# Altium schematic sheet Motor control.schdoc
size 438 x 304 mm
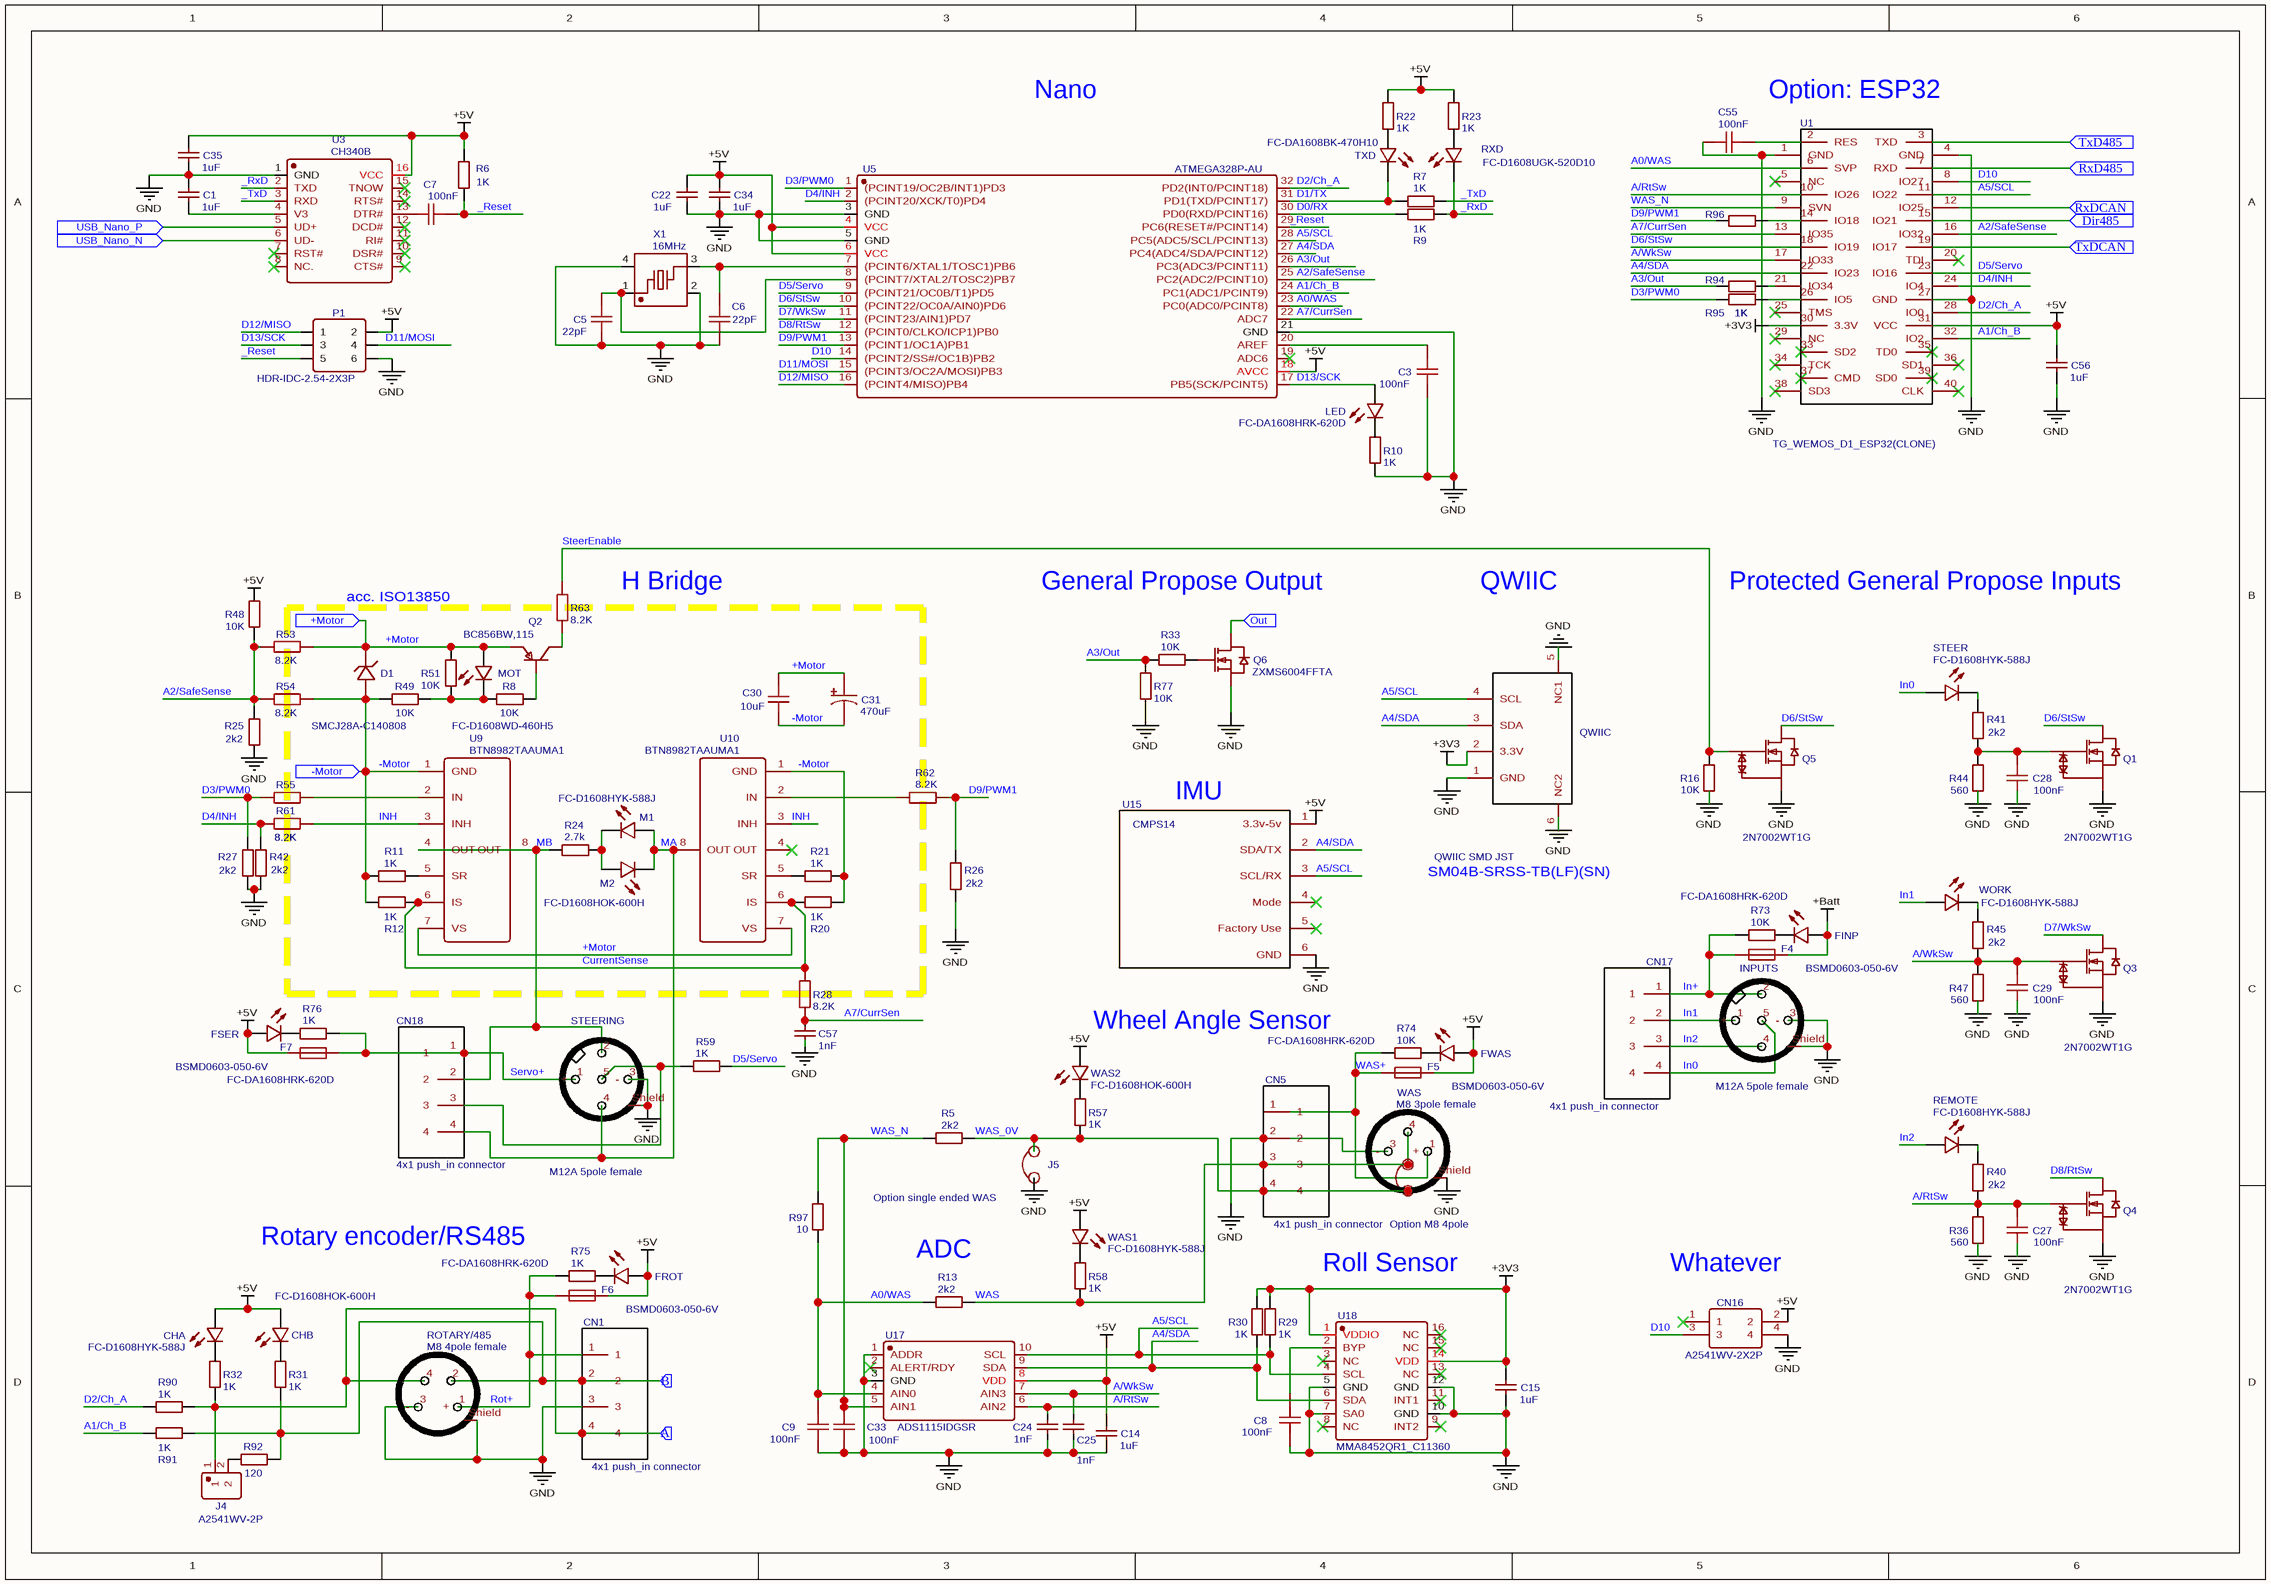
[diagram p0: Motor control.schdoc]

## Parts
C1  1uF  [C0603]
C3  100nF  [C0603]
C5  22pF  [C0603]
C6  22pF  [C0603]
C7  100nF  [C0603]
C8  100nF  [C0603]
C9  100nF  [C0603]
C14  1uF  [C0603]
C15  1uF  [C0603]
C22  1uF  [C0603]
C24  1nF  [C0603]
C25  1nF  [C0603]
C27  100nF  [C0603]
C28  100nF  [C0603]
C29  100nF  [C0603]
C30  10uF  [C1206]
C31  470uF  [CAP-SMD_BD10.0-L10.3-W10.3-FD]
C33  100nF  [C0603]
C34  1uF  [C0603]
C35  1uF  [C0603]
C55  100nF  [C0603]
C56  1uF  [C0603]
C57  1nF  [C0603]
CHA  FC-D1608HYK-588J  [LED0603-RD]
CHB  FC-D1608HOK-600H  [LED0603-RD]
CN1  4x1 push_in connector  [S2C-SMT 3.50/04/180G 3.5SN BK RL]
CN5  4x1 push_in connector  [S2C-SMT 3.50/04/180G 3.5SN BK RL]
CN16  A2541WV-2X2P  [HDR-TH_4P-P2.54-V-R2-C2-S2.54_A2541WV-2X2P]
CN17  4x1 push_in connector  [S2C-SMT 3.50/04/180G 3.5SN BK RL]
CN18  4x1 push_in connector  [S2C-SMT 3.50/04/180G 3.5SN BK RL]
D1  SMCJ28A-C140808  [SMC_L6.9-W5.9-LS7.9-RD]
F4  BSMD0603-050-6V  [F0603]
F5  BSMD0603-050-6V  [F0603]
F6  BSMD0603-050-6V  [F0603]
F7  BSMD0603-050-6V  [F0603]
FINP  FC-DA1608HRK-620D  [LED0603-FD]
FROT  FC-DA1608HRK-620D  [LED0603-FD]
FSER  FC-DA1608HRK-620D  [LED0603-FD]
FWAS  FC-DA1608HRK-620D  [LED0603-FD]
INPUTS  M12A 5pole female  [M12-A FEMALE 4-5POLE 90°]
J4  A2541WV-2P  [HDR-TH_P2.54-H-M_A2541WV-2P]
J5  Option single ended WAS  [1X02]
LED  FC-DA1608HRK-620D  [LED0603-FD]
M1  FC-D1608HYK-588J  [LED0603-RD]
M2  FC-D1608HOK-600H  [LED0603-RD]
MOT  FC-D1608WD-460H5  [LED0603-RD]
OP1  Option M8 4pole  [1X02]
P1  HDR-IDC-2.54-2X3P  [IDC-TH_6P-P2.54_C11214]
Q1  2N7002WT1G  [SOT-323-3_L2.0-W1.3-P1.30-LS2.1-BR]
Q2  BC856BW,115  [SOT-323-3_L2.2-W1.3-P1.30-LS2.2-BR]
Q3  2N7002WT1G  [SOT-323-3_L2.0-W1.3-P1.30-LS2.1-BR]
Q4  2N7002WT1G  [SOT-323-3_L2.0-W1.3-P1.30-LS2.1-BR]
Q5  2N7002WT1G  [SOT-323-3_L2.0-W1.3-P1.30-LS2.1-BR]
Q6  ZXMS6004FFTA  [SOT-23-3_L2.9-W1.6-P1.90-LS2.8-BR]
QWIIC  QWIIC SMD JST  [QWIIC CONNECTOR]
R5  2k2  [R0603]
R6  1K  [R0603]
R7  1K  [R0603]
R8  10K  [R0603]
R9  1K  [R0603]
R10  1K  [R0603]
R11  1K  [R0603]
R12  1K  [R0603]
R13  2k2  [R0603]
R16  10K  [R0603]
R20  1K  [R0603]
R21  1K  [R0603]
R22  1K  [R0603]
R23  1K  [R0603]
R24  2.7k  [R0603]
R25  2k2  [R0603]
R26  2k2  [R0603]
R27  2k2  [R0603]
R28  8.2K  [RES-SMD_L3.5-W1.5]
R29  1K  [R0603]
R30  1K  [R0603]
R31  1K  [R0603]
R32  1K  [R0603]
R33  10K  [R0603]
R36  560  [R0603]
R40  2k2  [R0603]
R41  2k2  [R0603]
R42  2k2  [R0603]
R44  560  [R0603]
R45  2k2  [R0603]
R47  560  [R0603]
R48  10K  [R0603]
R49  10K  [R0603]
R51  10K  [R0603]
R53  8.2K  [RES-SMD_L3.5-W1.5]
R54  8.2K  [RES-SMD_L3.5-W1.5]
R55  8.2K  [RES-SMD_L3.5-W1.5]
R57  1K  [R0603]
R58  1K  [R0603]
R59  1K  [R0603]
R61  8.2K  [RES-SMD_L3.5-W1.5]
R62  8.2K  [RES-SMD_L3.5-W1.5]
R63  8.2K  [RES-SMD_L3.5-W1.5]
R73  10K  [R0603]
R74  10K  [R0603]
R75  1K  [R0603]
R76  1K  [R0603]
R77  10K  [R0603]
R90  1K  [R0603]
R91  1K  [R0603]
R92  120  [R1206]
R94  1K  [R0603]
R95  1K  [R0603]
R96  1K  [R0603]
R97  10  [R0603]
REMOTE  FC-D1608HYK-588J  [LED0603-RD]
ROTARY/485  M8 4pole female  [M8 FEMALE 4POLE 90°]
RXD  FC-D1608UGK-520D10  [LED0603-RD]
STEER  FC-D1608HYK-588J  [LED0603-RD]
STEERING  M12A 5pole female  [M12-A FEMALE 4-5POLE 90°]
TXD  FC-DA1608BK-470H10  [LED0603-RD]
U1  TG_WEMOS_D1_ESP32(CLONE)  [WEMOS-D1 ESP32]
U3  CH340B  [SOIC-16_L9.9-W3.9-P1.27-LS6.0-BL]
U5  ATMEGA328P-AU  [TQFP-32_L7.0-W7.0-P0.80-LS9.0-BL]
U9  BTN8982TAAUMA1  [TO-263-7_L10.2-W10.4-P1.27-LS14.4-B]
U10  BTN8982TAAUMA1  [TO-263-7_L10.2-W10.4-P1.27-LS14.4-B]
U15  CMPS14  [CMPS14]
U17  ADS1115IDGSR  [MSOP-10_L3.0-W3.0-P0.50-LS5.0-BL]
U18  MMA8452QR1_C11360  [QFN-16_L3.0-W3.0-P0.50-TL_MMA8452QR1]
WAS  M8 3pole female  [M8 FEMALE 3POLE 90°]
WAS1  FC-D1608HYK-588J  [LED0603-RD]
WAS2  FC-D1608HOK-600H  [LED0603-RD]
WORK  FC-D1608HYK-588J  [LED0603-RD]
X1  16MHz  [OSC-SMD_4P-L2.0-W1.6-BL]

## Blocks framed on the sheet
H Bridge: C30 C31 D1 M1 M2 MOT Q2 R8 R11 R12 R20 R21 R24 R28 R49 R51 R53-R55 R61 U9 U10

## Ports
+Motor (in), -Motor (in), A (in), B (in), Dir485 (in), Out (in), RxD485 (in), RxDCAN (in), TxD485 (in), TxDCAN (in), USB_Nano_N (in), USB_Nano_P (in)

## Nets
+3V3: C15.1 QWIIC.2(3.3V) R29.2 R30.2 U1.30(3.3V) U18.1(VDDIO) U18.14(VDD)
+5V: C14.1 C22.1 C34.1 C35.1 C56.1 CHA.2(A) CHB.2(A) CN16.2 F5.1 F6.1 F7.1 FROT.1(A) FSER.1(A) FWAS.1(A) P1.2 R6.2 R22.2 R23.2 R48.1 U1.31(VCC) U3.16(VCC) U5.4(VCC) U5.6(VCC) U5.18(AVCC) U15.1(3.3v-5v) U17.8(VDD) WAS1.2(A) WAS2.2(A)
+Batt: F4.1 FINP.1(A)
GND: C1.1 C3.2 C5.1 C6.1 C8.1 C9.1 C14.2 C15.2 C22.2 C24.1 C25.1 C27.1 C28.1 C29.1 C33.1 C34.2 C35.2 C55.1 C56.2 C57.1 CN1.3 CN5.2 CN16.4 INPUTS.3(-) INPUTS.Shield J5.2 P1.6 Q1.2(S) Q3.2(S) Q4.2(S) Q5.2(S) Q6.2(S) QWIIC.1(GND) QWIIC.5(NC1) QWIIC.6(NC2) R10.1 R16.2 R25.2 R26.2 R27.2 R36.1 R42.2 R44.1 R47.1 R77.2 ROTARY/485.3(-) ROTARY/485.Shield STEERING.3(-) STEERING.Shield U1.1(GND) U1.4(GND) U1.27(GND) U3.1(GND) U5.3(GND) U5.5(GND) U5.21(GND) U15.6(GND) U17.1(ADDR) U17.3(GND) U18.5(GND) U18.7(SA0) U18.10(GND) U18.12(GND) WAS.3(-) WAS.Shield X1.2(GND) X1.4(GND)
+Motor: C30.2 C31.1 D1.1(C) MOT.2(+) Q2.2 R51.2 R53.2 U9.7(VS) U10.7(VS) ; port +Motor
-Motor: C30.1 C31.2 D1.2(A) R11.1 R12.1 R20.2 R21.2 R49.1 R54.2 U9.1(GND) U10.1(GND) ; port -Motor
_Reset: C7.1 P1.5 R6.1 U5.29(PC6(RESET#/PCINT14))
_RxD: R9.2 RXD.1(K) U3.2(TXD)
_TxD: R7.1 U3.3(RXD)
A: CN1.4 J4.1 R32.1 R90.1 ROTARY/485.4 ; port A
A0/WAS: C9.2 R13.1 R97.2 U1.6(SVP) U5.23(PC0(ADC0/PCINT8)) U17.4(AIN0)
A1/Ch_B: R91.2 U1.32(IO2) U5.24(PC1(ADC1/PCINT9))
A2/SafeSense: R25.1 R48.2 R53.1 R54.1 U1.16(IO32) U5.25(PC2(ADC2/PCINT10))
A3/Out: R33.2 R77.1 R94.2 U5.26(PC3(ADC3/PCINT11))
A4/SDA: QWIIC.3(SDA) R30.1 U1.22(IO23) U5.27(PC4(ADC4/SDA/PCINT12)) U15.2(SDA/TX) U17.9(SDA) U18.6(SDA)
A5/SCL: QWIIC.4(SCL) R29.1 U1.11(IO22) U5.28(PC5(ADC5/SCL/PCINT13)) U15.3(SCL/RX) U17.10(SCL) U18.4(SCL)
A7/CurrSen: C57.2 R28.1 U1.13(IO35) U5.22(ADC7)
A/RtSw: C24.2 C27.2 Q4.1(G) R36.2 R40.2 U1.10(IO26) U17.6(AIN2)
A/WkSw: C25.2 C29.2 Q3.1(G) R45.2 R47.2 U1.17(IO33) U17.7(AIN3)
B: CN1.2 R31.1 R91.1 R92.2 ROTARY/485.2 ; port B
CurrentSense: R12.2 R20.1 R28.2 U9.6(IS) U10.6(IS)
D0/RX: R9.1 U5.30(PD0(RXD/PCINT16))
D1/TX: R7.2 TXD.1(-) U5.31(PD1(TXD/PCINT17))
D2/Ch_A: R90.2 U1.28(IO0) U5.32(PD2(INT0/PCINT18))
D3/PWM0: R27.1 R55.1 R95.2 U5.1((PCINT19/OC2B/INT1)PD3)
D4/INH: R42.1 R61.1 U1.24(IO4) U5.2((PCINT20/XCK/T0)PD4)
D5/Servo: R59.1 U1.23(IO16) U5.9((PCINT21/OC0B/T1)PD5)
D6/StSw: Q1.3(D) Q5.3(D) U1.18(IO19) U5.10((PCINT22/OC0A/AIN0)PD6)
D7/WkSw: Q3.3(D) U5.11((PCINT23/AIN1)PD7)
D8/RtSw: Q4.3(D) U5.12((PCINT0/CLKO/ICP1)PB0)
D9/PWM1: R26.1 R62.2 R96.2 U5.13((PCINT1/OC1A)PB1)
D10: CN16.3 U1.8(IO27) U5.14((PCINT2/SS#/OC1B)PB2)
D11/MOSI: P1.4 U5.15((PCINT3/OC2A/MOSI)PB3)
D12/MISO: P1.1 U5.16((PCINT4/MISO)PB4)
D13/SCK: LED.1(A) P1.3 U5.17(PB5(SCK/PCINT5))
Dir485: U1.15(IO21) ; port Dir485
In0: CN17.4 INPUTS.5 STEER.2(A)
In1: CN17.2 INPUTS.1(+) WORK.2(A)
In2: CN17.3 INPUTS.4 REMOTE.2(A)
In+: CN17.1 F4.2 INPUTS.2 R73.2
INH: R61.2 U9.3(INH) U10.3(INH)
MA: CN18.4 M1.2(A) M2.1(K) STEERING.4 U10.8(OUT)
MB: CN18.2 R24.2 STEERING.2 U9.4(OUT) U9.8(OUT)
Out: Q6.3(D) ; port Out
Rot+: CN1.1 F6.2 R75.2 ROTARY/485.1(+)
RxD485: U1.7(RXD) ; port RxD485
RxDCAN: U1.12(IO25) ; port RxDCAN
Servo+: CN18.1 F7.2 R76.1 STEERING.1(+)
SteerEnable: Q5.1(G) R16.1 R63.2
TxD485: U1.3(TXD) ; port TxD485
TxDCAN: U1.19(IO17) ; port TxDCAN
USB_Nano_N: U3.6(UD-) ; port USB_Nano_N
USB_Nano_P: U3.5(UD+) ; port USB_Nano_P
WAS: CN5.3 OP1.1 R13.2 R58.1 WAS.4
WAS+: CN5.1 F5.2 R74.2 WAS.1(+)
WAS_0V: CN5.4 J5.1 OP1.2 R5.2 R57.1
WAS_N: C33.2 R5.1 R97.1 U1.9(SVN) U17.5(AIN1)
NetC1_2: C1.2 U3.4(V3)
NetC3_1: C3.1 U5.20(AREF)
NetC5_2: C5.2 U5.8((PCINT7/XTAL2/TOSC2)PB7) X1.1
NetC6_2: C6.2 U5.7((PCINT6/XTAL1/TOSC1)PB6) X1.3
NetC7_2: C7.2 U3.13(DTR#)
NetC8_2: C8.2 U18.2(BYP)
NetC28_2: C28.2 Q1.1(G) R41.2 R44.2
NetC55_2: C55.2 U1.2(RES)
NetCHA_1: CHA.1(K) R32.2
NetCHB_1: CHB.1(K) R31.2
NetCN18_3: CN18.3 R59.2 STEERING.5
NetFINP_2: FINP.2(K) R73.1
NetFROT_2: FROT.2(K) R75.1
NetFSER_2: FSER.2(K) R76.2
NetFWAS_2: FWAS.2(K) R74.1
NetJ4_2: J4.2 R92.1
NetLED_2: LED.2(K) R10.2
NetM1_1: M1.1(K) M2.2(A) R24.1
NetMOT_1: MOT.1(-) R8.1 R49.2 R51.1
NetQ2_1: Q2.1 R8.2
NetQ2_3: Q2.3 R63.1
NetQ6_1: Q6.1(G) R33.1
NetR11_2: R11.2 U9.5(SR)
NetR21_1: R21.1 U10.5(SR)
NetR22_1: R22.1 TXD.2(+)
NetR23_1: R23.1 RXD.2(A)
NetR40_1: R40.1 REMOTE.1(K)
NetR41_1: R41.1 STEER.1(K)
NetR45_1: R45.1 WORK.1(K)
NetR55_2: R55.2 U9.2(IN)
NetR57_2: R57.2 WAS2.1(K)
NetR58_2: R58.2 WAS1.1(K)
NetR62_1: R62.1 U10.2(IN)
NetR94_1: R94.1 U1.21(IO34)
NetR95_1: R95.1 U1.26(IO5)
NetR96_1: R96.1 U1.14(IO18)

Not connected (* = marked no-connect by the designer): CN16 1*; U1 5(NC)* 20(TDI)* 25(TMS)* 29(NC)* 33(SD2)* 34(TCK)* 35(TD0)* 36(SD1)* 37(CMD)* 38(SD3)* 39(SD0)* 40(CLK)*; U3 7(RST#)* 8(NC.)* 9(CTS#)* 10(DSR#)* 11(RI#)* 12(DCD#)* 14(RTS#)* 15(TNOW)*; U5 19(ADC6)*; U10 4(OUT)*; U15 4(Mode)* 5(Factory_Use)*; U17 2(ALERT/RDY)*; U18 3(NC)* 8(NC)* 9(INT2)* 11(INT1)* 13(NC)* 15(NC)* 16(NC)*

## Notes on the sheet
- Nano
- Option: ESP32
- acc. ISO13850
- General Propose Output
- QWIIC
- Protected General Propose Inputs
- SM04B-SRSS-TB(LF)(SN)
- Wheel Angle Sensor
- Rotary encoder/RS485
- (near R13) ADC
- Roll Sensor
- (near CN16) Whatever

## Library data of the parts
C1 C14 C15 C22 C34 C35 C56 = 1uF: BOM_Manufacturer Part: CL10A105KP8NNNC; BOM_Manufacturer: SAMSUNG; nameAlias: Capacitance
C3 C7-C9 C27-C29 C33 C55 = 100nF: BOM_Manufacturer: YAGEO; BOM_Manufacturer Part: CC0603JRX7R8BB104; nameAlias: Capacitance; Contributor: LCSC
C5 C6 = 22pF: BOM_Manufacturer: CCTC; BOM_Manufacturer Part: TCC0603COG220J500CT; nameAlias: Capacitance; Contributor: LCSC
C24 C25 C57 = 1nF: BOM_Manufacturer: FH(Guangdong Fenghua Advanced Tech); BOM_Manufacturer Part: 0603CG102F500NT; nameAlias: Capacitance; Contributor: LCSC
C30 = 10uF: BOM_Manufacturer: CCTC; BOM_Manufacturer Part: TCC1206X7R106K250HT; nameAlias: Capacitance; Contributor: LCSC
C31 = 470uF: BOM_Manufacturer: CapXon; BOM_Manufacturer Part: HV471M016F105R; nameAlias: Capacitance; Contributor: LCSC
CHA M1 REMOTE STEER WAS1 WORK = FC-D1608HYK-588J: BOM_Manufacturer: NATIONSTAR; SMT Type: Extend
CHB M2 WAS2 = FC-D1608HOK-600H: BOM_Manufacturer: NATIONSTAR; SMT Type: Extend
CN1 CN5 CN17 CN18 = 4x1 push_in connector: BOM_Manufacturer: Weidmuller; BOM_Manufacturer Part: 1825660000; Contributor: Renaud Varin
CN16 = A2541WV-2X2P: BOM_Manufacturer: Changjiang Connectors; Contributor: LCSC
D1 = SMCJ28A-C140808: BOM_Manufacturer: Yenji; Contributor: LCSC
F4-F7 = BSMD0603-050-6V: BOM_Manufacturer: BHFUSE; Contributor: LCSC
FINP FROT FSER FWAS LED = FC-DA1608HRK-620D: BOM_Manufacturer: NATIONSTAR
INPUTS STEERING = M12A 5pole female: BOM_Manufacturer: Binder, Escha; Contributor: GoRoNb
J4 = A2541WV-2P: BOM_Manufacturer: CJT(Changjiang Connectors); Contributor: LCSC
J5 = Option single ended WAS: Contributor: KiCad
MOT = FC-D1608WD-460H5: BOM_Manufacturer: NATIONSTAR; SMT Type: Extend
OP1 = Option M8 4pole: Contributor: KiCad
P1 = HDR-IDC-2.54-2X3P: BOM_Manufacturer: BOOMELE; BOM_Manufacturer Part: 2X3 2.54mm IDC Box
Q1 Q3-Q5 = 2N7002WT1G: BOM_Manufacturer: ON Semicon; Contributor: LCSC; SMT Type: Extend
Q2 = BC856BW,115: BOM_Manufacturer: Nexperia; SMT Type: Extend
Q6 = ZXMS6004FFTA: BOM_Manufacturer: Diodes Incorporated; Contributor: LCSC
QWIIC = QWIIC SMD JST: BOM_Manufacturer: JST Sales America; BOM_Manufacturer Part: SM04B-SRSS-TB(LF)(SN); Contributor: donhagen
R5 R13 R25-R27 R40-R42 R45 = 2k2: BOM_Manufacturer: RALEC; BOM_Manufacturer Part: RTT03222JTP; nameAlias: Resistance (Ohms)
R6 R7 R9-R12 R20-R23 R29-R32 R57-R59 R75 R76 R90 R91 R94-R96 = 1K: BOM_Manufacturer: RALEC; BOM_Manufacturer Part: RTT03102JTP; nameAlias: Resistance (Ohms)
R8 R16 R33 R48 R49 R51 R73 R74 R77 = 10K: BOM_Manufacturer: RALEC; BOM_Manufacturer Part: RTT03103JTP; nameAlias: Resistance (Ohms)
R24 = 2.7k: BOM_Manufacturer: RALEC; BOM_Manufacturer Part: RTT03272JTP; nameAlias: Resistance (Ohms)
R28 R53-R55 R61-R63 = 8.2K: BOM_Manufacturer: Thunder Component; BOM_Manufacturer Part: MElF-MFR02041/4WS130ΩFT50; Contributor: LCSC; nameAlias: Resistance (Ohms)
R36 R44 R47 = 560: BOM_Manufacturer: RALEC; BOM_Manufacturer Part: RTT03561JTP; nameAlias: Resistance (Ohms)
R92 = 120: BOM_Manufacturer: RALEC; BOM_Manufacturer Part: RTT06121JTP; nameAlias: Resistance (Ohms)
R97 = 10: BOM_Manufacturer: RALEC; BOM_Manufacturer Part: RTT03100JTP; nameAlias: Resistance (Ohms)
ROTARY/485 = M8 4pole female: BOM_Manufacturer: Binder, Escha; Contributor: GoRoNb
RXD = FC-D1608UGK-520D10: BOM_Manufacturer: NATIONSTAR; SMT Type: Extend
TXD = FC-DA1608BK-470H10: BOM_Manufacturer: NATIONSTAR
U1 = TG_WEMOS_D1_ESP32(CLONE): BOM_Manufacturer Part: New SchematicLib; Contributor: John Archbold
U3 = CH340B: BOM_Manufacturer: WCH
U5 = ATMEGA328P-AU: BOM_Manufacturer: MICROCHIP; SMT Type: Basic
U9 U10 = BTN8982TAAUMA1: BOM_Manufacturer: Infineon
U15 = CMPS14: Contributor: FixyNeko
U17 = ADS1115IDGSR: BOM_Manufacturer: TI; SMT Type: Extend
U18 = MMA8452QR1_C11360: BOM_Manufacturer: FREESCALE; SMT Type: Extend
WAS = M8 3pole female: BOM_Manufacturer: Binder, Escha; Contributor: GoRoNb
X1 = 16MHz: BOM_Manufacturer: Yangxing Tech; BOM_Manufacturer Part: X201616MPB4SC; nameAlias: Frequency; Contributor: LCSC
